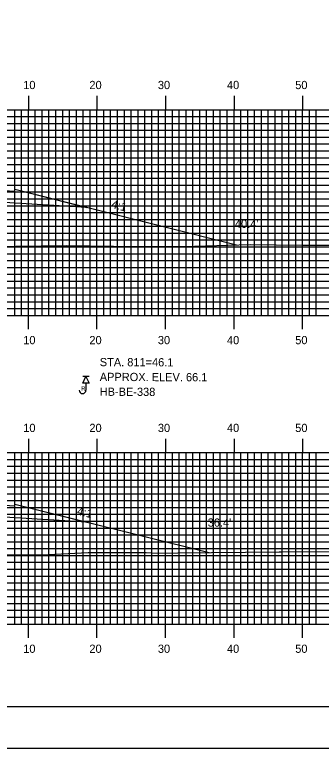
# Model space of a CAD drawing. Extents: x 2059 to 2403, y -1658 to -1438.
# Drawn here: x 2233.2 to 2277.9, y -1657.7 to -1550.7 of the extents above; entities that cross this region are included whole.
import ezdxf

# ---------------------------------------------------------------- set-up
doc = ezdxf.new("R2010")
doc.units = 0
for name, color, linetype in [('ANNOTATION', 7, 'Continuous'), ('BORDER', 7, 'Continuous'), ('BORING - REFUSAL', 7, 'Continuous'), ('D_Roadway_SlopeLines', 7, 'Continuous'), ('D_Roadway_SubGrade', 7, 'Continuous'), ('D_Text_Standard', 7, 'Continuous'), ('H_V ANNOTATION', 7, 'Continuous'), ('MAJOR', 7, 'Continuous'), ('MINOR', 7, 'Continuous'), ('PLOT BOUNDARY', 7, 'Continuous'), ('S_Roadway_Centerline', 7, 'Continuous')]:
    doc.layers.add(name, color=color, linetype=linetype)

msp = doc.modelspace()

# ---------------------------------------------------------------- linework, layer by layer
at = {"layer": 'BORDER'}
msp.add_lwpolyline([(2075.59, -1651.6), (2395.59, -1651.6), (2395.59, -1441.6), (2075.59, -1441.6)], close=True, dxfattribs=at)
at = {"layer": 'BORING - REFUSAL'}
for p, q in [((2244.07, -1603.5), (2243.11, -1603.5)), ((2243.59, -1604.46), (2243.59, -1605.52))]:
    msp.add_line(p, q, dxfattribs=at)
msp.add_lwpolyline([(2243.59, -1603.5), (2244.07, -1604.46), (2243.11, -1604.46)], close=True, dxfattribs=at)
msp.add_arc((2243.1, -1605.52), 0.485, 180, 0, dxfattribs=at)
at = {"layer": 'D_Roadway_SlopeLines'}
for points in [[(2233.19, -1576.21), (2265.57, -1584.31)], [(2233.19, -1622.1), (2261.54, -1629.19)]]:
    msp.add_lwpolyline(points, dxfattribs=at)
at = {"layer": 'D_Roadway_SubGrade'}
for points in [[(2225.19, -1576.23), (2225.19, -1575.98), (2233.19, -1576.46), (2233.19, -1576.21), (2243.71, -1578.85), (2225.19, -1577.73)], [(2225.19, -1622.12), (2225.19, -1621.87), (2233.19, -1622.35), (2233.19, -1622.1), (2243.71, -1624.73), (2225.19, -1623.62)]]:
    msp.add_lwpolyline(points, close=True, dxfattribs=at)
at = {"layer": 'MAJOR'}
for p, q in [((2235.19, -1562.6), (2235.19, -1564.6)), ((2245.19, -1562.6), (2245.19, -1564.6)), ((2255.19, -1562.6), (2255.19, -1564.6)), ((2265.19, -1562.6), (2265.19, -1564.6)), ((2275.19, -1562.6), (2275.19, -1564.6)), ((2085.19, -1564.6), (2365.19, -1564.6)), ((2085.19, -1564.6), (2365.19, -1564.6)), ((2235.19, -1594.6), (2235.19, -1564.6)), ((2245.19, -1594.6), (2245.19, -1564.6)), ((2255.19, -1594.6), (2255.19, -1564.6)), ((2265.19, -1594.6), (2265.19, -1564.6)), ((2275.19, -1594.6), (2275.19, -1564.6)), ((2085.19, -1569.6), (2365.19, -1569.6)), ((2085.19, -1574.6), (2365.19, -1574.6)), ((2085.19, -1579.6), (2365.19, -1579.6)), ((2085.19, -1584.6), (2365.19, -1584.6)), ((2085.19, -1589.6), (2365.19, -1589.6)), ((2085.19, -1594.6), (2365.19, -1594.6)), ((2085.19, -1594.6), (2365.19, -1594.6)), ((2235.19, -1596.61), (2235.19, -1594.6)), ((2245.19, -1596.61), (2245.19, -1594.6)), ((2255.19, -1596.61), (2255.19, -1594.6)), ((2265.19, -1596.61), (2265.19, -1594.6)), ((2275.19, -1596.61), (2275.19, -1594.6)), ((2235.19, -1612.6), (2235.19, -1614.6)), ((2245.19, -1612.6), (2245.19, -1614.6)), ((2255.19, -1612.6), (2255.19, -1614.6)), ((2265.19, -1612.6), (2265.19, -1614.6)), ((2275.19, -1612.6), (2275.19, -1614.6)), ((2085.19, -1614.6), (2365.19, -1614.6)), ((2085.19, -1614.6), (2365.19, -1614.6)), ((2235.19, -1639.6), (2235.19, -1614.6)), ((2245.19, -1639.6), (2245.19, -1614.6)), ((2255.19, -1639.6), (2255.19, -1614.6)), ((2265.19, -1639.6), (2265.19, -1614.6)), ((2275.19, -1639.6), (2275.19, -1614.6)), ((2085.19, -1619.6), (2365.19, -1619.6)), ((2085.19, -1624.6), (2365.19, -1624.6)), ((2085.19, -1629.6), (2365.19, -1629.6)), ((2085.19, -1634.6), (2365.19, -1634.6)), ((2085.19, -1639.6), (2365.19, -1639.6)), ((2085.19, -1639.6), (2365.19, -1639.6)), ((2235.19, -1641.61), (2235.19, -1639.6)), ((2245.19, -1641.61), (2245.19, -1639.6)), ((2255.19, -1641.61), (2255.19, -1639.6)), ((2265.19, -1641.61), (2265.19, -1639.6)), ((2275.19, -1641.61), (2275.19, -1639.6))]:
    msp.add_line(p, q, dxfattribs=at)
at = {"layer": 'MINOR'}
for p, q in [((2233.19, -1594.6), (2233.19, -1564.6)), ((2234.19, -1594.6), (2234.19, -1564.6)), ((2236.19, -1594.6), (2236.19, -1564.6)), ((2237.19, -1594.6), (2237.19, -1564.6)), ((2238.19, -1594.6), (2238.19, -1564.6)), ((2239.19, -1594.6), (2239.19, -1564.6)), ((2240.19, -1594.6), (2240.19, -1564.6)), ((2241.19, -1594.6), (2241.19, -1564.6)), ((2242.19, -1594.6), (2242.19, -1564.6)), ((2243.19, -1594.6), (2243.19, -1564.6)), ((2244.19, -1594.6), (2244.19, -1564.6)), ((2246.19, -1594.6), (2246.19, -1564.6)), ((2247.19, -1594.6), (2247.19, -1564.6)), ((2248.19, -1594.6), (2248.19, -1564.6)), ((2249.19, -1594.6), (2249.19, -1564.6)), ((2250.19, -1594.6), (2250.19, -1564.6)), ((2251.19, -1594.6), (2251.19, -1564.6)), ((2252.19, -1594.6), (2252.19, -1564.6)), ((2253.19, -1594.6), (2253.19, -1564.6)), ((2254.19, -1594.6), (2254.19, -1564.6)), ((2256.19, -1594.6), (2256.19, -1564.6)), ((2257.19, -1594.6), (2257.19, -1564.6)), ((2258.19, -1594.6), (2258.19, -1564.6)), ((2259.19, -1594.6), (2259.19, -1564.6)), ((2260.19, -1594.6), (2260.19, -1564.6)), ((2261.19, -1594.6), (2261.19, -1564.6)), ((2262.19, -1594.6), (2262.19, -1564.6)), ((2263.19, -1594.6), (2263.19, -1564.6)), ((2264.19, -1594.6), (2264.19, -1564.6)), ((2266.19, -1594.6), (2266.19, -1564.6)), ((2267.19, -1594.6), (2267.19, -1564.6)), ((2268.19, -1594.6), (2268.19, -1564.6)), ((2269.19, -1594.6), (2269.19, -1564.6)), ((2270.19, -1594.6), (2270.19, -1564.6)), ((2271.19, -1594.6), (2271.19, -1564.6)), ((2272.19, -1594.6), (2272.19, -1564.6)), ((2273.19, -1594.6), (2273.19, -1564.6)), ((2274.19, -1594.6), (2274.19, -1564.6)), ((2276.19, -1594.6), (2276.19, -1564.6)), ((2277.19, -1594.6), (2277.19, -1564.6)), ((2085.19, -1565.6), (2365.19, -1565.6)), ((2085.19, -1566.6), (2365.19, -1566.6)), ((2085.19, -1567.6), (2365.19, -1567.6)), ((2085.19, -1568.6), (2365.19, -1568.6)), ((2085.19, -1570.6), (2365.19, -1570.6)), ((2085.19, -1571.6), (2365.19, -1571.6)), ((2085.19, -1572.6), (2365.19, -1572.6)), ((2085.19, -1573.6), (2365.19, -1573.6)), ((2085.19, -1575.6), (2365.19, -1575.6)), ((2085.19, -1576.6), (2365.19, -1576.6)), ((2085.19, -1577.6), (2365.19, -1577.6)), ((2085.19, -1578.6), (2365.19, -1578.6)), ((2085.19, -1580.6), (2365.19, -1580.6)), ((2085.19, -1581.6), (2365.19, -1581.6)), ((2085.19, -1582.6), (2365.19, -1582.6)), ((2085.19, -1583.6), (2365.19, -1583.6)), ((2085.19, -1585.6), (2365.19, -1585.6)), ((2085.19, -1586.6), (2365.19, -1586.6)), ((2085.19, -1587.6), (2365.19, -1587.6)), ((2085.19, -1588.6), (2365.19, -1588.6)), ((2085.19, -1590.6), (2365.19, -1590.6)), ((2085.19, -1591.6), (2365.19, -1591.6)), ((2085.19, -1592.6), (2365.19, -1592.6)), ((2085.19, -1593.6), (2365.19, -1593.6)), ((2233.19, -1639.6), (2233.19, -1614.6)), ((2234.19, -1639.6), (2234.19, -1614.6)), ((2236.19, -1639.6), (2236.19, -1614.6)), ((2237.19, -1639.6), (2237.19, -1614.6)), ((2238.19, -1639.6), (2238.19, -1614.6)), ((2239.19, -1639.6), (2239.19, -1614.6)), ((2240.19, -1639.6), (2240.19, -1614.6)), ((2241.19, -1639.6), (2241.19, -1614.6)), ((2242.19, -1639.6), (2242.19, -1614.6)), ((2243.19, -1639.6), (2243.19, -1614.6)), ((2244.19, -1639.6), (2244.19, -1614.6)), ((2246.19, -1639.6), (2246.19, -1614.6)), ((2247.19, -1639.6), (2247.19, -1614.6)), ((2248.19, -1639.6), (2248.19, -1614.6)), ((2249.19, -1639.6), (2249.19, -1614.6)), ((2250.19, -1639.6), (2250.19, -1614.6)), ((2251.19, -1639.6), (2251.19, -1614.6)), ((2252.19, -1639.6), (2252.19, -1614.6)), ((2253.19, -1639.6), (2253.19, -1614.6)), ((2254.19, -1639.6), (2254.19, -1614.6)), ((2256.19, -1639.6), (2256.19, -1614.6)), ((2257.19, -1639.6), (2257.19, -1614.6)), ((2258.19, -1639.6), (2258.19, -1614.6)), ((2259.19, -1639.6), (2259.19, -1614.6)), ((2260.19, -1639.6), (2260.19, -1614.6)), ((2261.19, -1639.6), (2261.19, -1614.6)), ((2262.19, -1639.6), (2262.19, -1614.6)), ((2263.19, -1639.6), (2263.19, -1614.6)), ((2264.19, -1639.6), (2264.19, -1614.6)), ((2266.19, -1639.6), (2266.19, -1614.6)), ((2267.19, -1639.6), (2267.19, -1614.6)), ((2268.19, -1639.6), (2268.19, -1614.6)), ((2269.19, -1639.6), (2269.19, -1614.6)), ((2270.19, -1639.6), (2270.19, -1614.6)), ((2271.19, -1639.6), (2271.19, -1614.6)), ((2272.19, -1639.6), (2272.19, -1614.6)), ((2273.19, -1639.6), (2273.19, -1614.6)), ((2274.19, -1639.6), (2274.19, -1614.6)), ((2276.19, -1639.6), (2276.19, -1614.6)), ((2277.19, -1639.6), (2277.19, -1614.6)), ((2085.19, -1615.6), (2365.19, -1615.6)), ((2085.19, -1616.6), (2365.19, -1616.6)), ((2085.19, -1617.6), (2365.19, -1617.6)), ((2085.19, -1618.6), (2365.19, -1618.6)), ((2085.19, -1620.6), (2365.19, -1620.6)), ((2085.19, -1621.6), (2365.19, -1621.6)), ((2085.19, -1622.6), (2365.19, -1622.6)), ((2085.19, -1623.6), (2365.19, -1623.6)), ((2085.19, -1625.6), (2365.19, -1625.6)), ((2085.19, -1626.6), (2365.19, -1626.6)), ((2085.19, -1627.6), (2365.19, -1627.6)), ((2085.19, -1628.6), (2365.19, -1628.6)), ((2085.19, -1630.6), (2365.19, -1630.6)), ((2085.19, -1631.6), (2365.19, -1631.6)), ((2085.19, -1632.6), (2365.19, -1632.6)), ((2085.19, -1633.6), (2365.19, -1633.6)), ((2085.19, -1635.6), (2365.19, -1635.6)), ((2085.19, -1636.6), (2365.19, -1636.6)), ((2085.19, -1637.6), (2365.19, -1637.6)), ((2085.19, -1638.6), (2365.19, -1638.6))]:
    msp.add_line(p, q, dxfattribs=at)
at = {"layer": 'PLOT BOUNDARY'}
msp.add_lwpolyline([(2059.4, -1657.72), (2399.4, -1657.72), (2399.4, -1437.72), (2059.4, -1437.72)], close=True, dxfattribs=at)
at = {"layer": 'S_Roadway_Centerline'}
for points in [[(2155.58, -1585.48), (2171.86, -1585.54), (2183.8, -1584.91), (2191.16, -1584.63), (2200.71, -1584.67), (2204.03, -1584.7), (2204.99, -1584.67), (2207.3, -1584.66), (2223.45, -1584.5), (2229.59, -1584.56), (2240.77, -1584.4), (2247.61, -1584.49), (2257.78, -1584.56), (2267.55, -1584.25), (2275.14, -1584.38), (2280.43, -1584.34)], [(2165.86, -1630.74), (2169.87, -1630.62), (2171.98, -1630.57), (2185.47, -1630.4), (2199.17, -1630.2), (2202.88, -1630.06), (2207.59, -1629.97), (2220.32, -1629.49), (2228.8, -1629.48), (2237.12, -1629.51), (2243.9, -1629.19), (2252.38, -1629.15), (2254.15, -1629.29), (2256.97, -1629.24), (2271.79, -1629.07), (2272.13, -1629.07), (2287.23, -1628.99)]]:
    msp.add_lwpolyline(points, dxfattribs=at)

# ---------------------------------------------------------------- texts
at = {"layer": 'ANNOTATION'}
for p in [(2247.2, -1578.91), (2242.2, -1623.63)]:
    msp.add_text('4:1', height=1.2, rotation=345.9638, dxfattribs=at).set_placement(p)
at = {"layer": 'BORING - REFUSAL'}
for s, p in [('STA. 811=46.1', (2245.6, -1602)), ('APPROX. ELEV. 66.1', (2245.6, -1604.16)), ('HB-BE-338', (2245.59, -1606.32))]:
    msp.add_text(s, height=1.2, rotation=359.8142, dxfattribs=at).set_placement(p)
msp.add_text('R', height=0.64, dxfattribs=at).set_placement((2242.88, -1605.58))
at = {"layer": 'D_Text_Standard'}
for s, p in [("40.4'", (2265.32, -1581.84)), ("36.4'", (2261.35, -1625.4))]:
    msp.add_text(s, height=1.2, dxfattribs=at).set_placement(p)
at = {"layer": 'H_V ANNOTATION'}
for s, p in [('10', (2234.44, -1561.6)), ('20', (2244.09, -1561.6)), ('30', (2254.08, -1561.6)), ('40', (2264.16, -1561.6)), ('50', (2274.12, -1561.6)), ('10', (2234.44, -1598.8)), ('20', (2244.09, -1598.8)), ('30', (2254.08, -1598.8)), ('40', (2264.16, -1598.8)), ('50', (2274.12, -1598.8)), ('10', (2234.44, -1611.6)), ('20', (2244.09, -1611.6)), ('30', (2254.08, -1611.6)), ('40', (2264.16, -1611.6)), ('50', (2274.12, -1611.6)), ('10', (2234.44, -1643.8)), ('20', (2244.09, -1643.8)), ('30', (2254.08, -1643.8)), ('40', (2264.16, -1643.8)), ('50', (2274.12, -1643.8))]:
    msp.add_text(s, height=1.2, dxfattribs=at).set_placement(p)

doc.saveas('drawing.dxf')
